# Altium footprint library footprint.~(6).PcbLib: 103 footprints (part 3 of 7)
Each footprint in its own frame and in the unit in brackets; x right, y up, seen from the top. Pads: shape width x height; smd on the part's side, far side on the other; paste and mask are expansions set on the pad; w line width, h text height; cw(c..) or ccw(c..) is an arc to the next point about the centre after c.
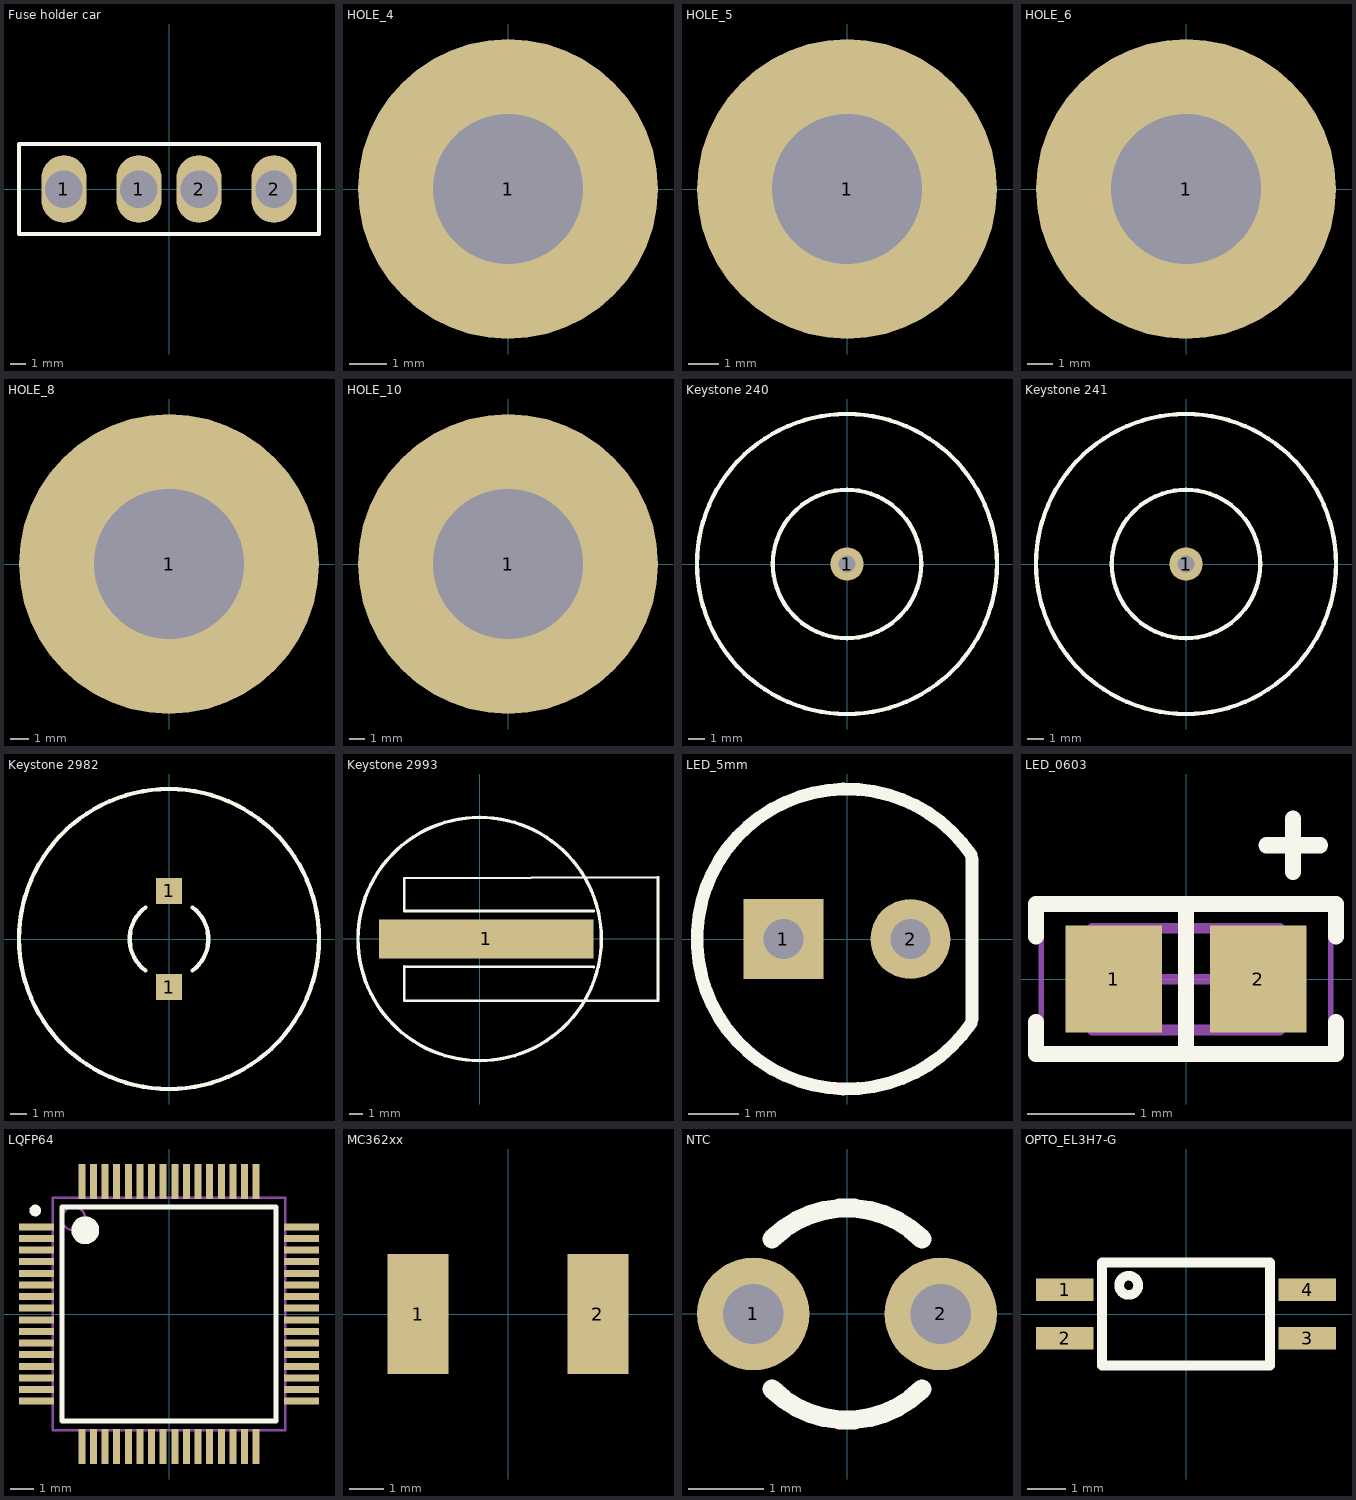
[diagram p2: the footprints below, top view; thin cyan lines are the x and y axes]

## Fuse holder car [mm] "Car fuse holder"
height 8
pads (4):
  oval 3x4.5 hole 2.5: 1(-7,0) 1(-2,0) 2(2,0) 2(7,0)
Top Overlay:
  lines w0.254: -10,-3 10,-3 10,3 -10,3 -10,-3
3D body: height 20, standoff 0, extent -9.5,-2.5 9.5,2.5

## HOLE_4 [mm] "Hole for M4 screw"
pads (1):
  round 8 hole 4: 1(0,0)

## HOLE_5 [mm] "Hole for M5 screw"
pads (1):
  round 10 hole 5: 1(0,0)

## HOLE_6 [mm] "Hole for M6 screw"
pads (1):
  round 12 hole 6: 1(0,0)

## HOLE_8 [mm] "Hole for M8 screw"
pads (1):
  round 16 hole 8: 1(0,0)

## HOLE_10 [mm] "Hole for M10 screw"
pads (1):
  round 20 hole 10: 1(0,0)

## Keystone 240 [mm] "Battery contact Keystone 240"
height 7.6
pads (1):
  round 2 hole 1: 1(0,0)
Top Overlay:
  circle w0.254: c0,0 r9
  circle w0.254: c0,0 r4.45
3D body: height 7.6, standoff 0, extent -4.45,-4.447 4.45,4.447

## Keystone 241 [mm] "Battery contact Keystone 241"
height 1.41
pads (1):
  round 2 hole 1: 1(0,0)
Top Overlay:
  circle w0.254: c0,0 r9
  circle w0.254: c0,0 r4.45
3D body: height 1.41, standoff 0, extent -4.45,-4.447 4.45,4.447

## Keystone 2982 [mil] "Battery contact Keystone 2982"
height 16
pads (2):
  rect 62x62 smd: 1(0,-113.5) 1(0,113.5)
Top Overlay:
  circle w10: c0,0 r354.33
  lines w10: -55.8,-74.4 cw(c0,0) -55.8,74.4 ; 55.8,-74.4 ccw(c0,0) 55.8,74.4
3D body: height 8, standoff 0, extent -31,80 31,144.5
3D body: height 16, standoff 8, extent -92.99,-92.99 93,93
3D body: height 8, standoff 0, extent -31,-144.5 31,-80

## Keystone 2993 [mm] "Battery contact Keystone 2993"
height 2.667
pads (1):
  rect 15.88x2.85 smd: 1(0.49,0)
Top Overlay:
  circle w0.254: c0,0 r9
  lines w0.1: 8.43,-2.07 -5.57,-2.03 -5.57,-4.5 -5.57,-4.57 13.19,-4.57 13.19,4.5 13.19,4.57 -5.57,4.5 -5.57,2.07 8.43,2.07
  lines w0.2: 8.43,-2.07 -5.57,-2.03 -5.57,-4.57 13.19,-4.57 13.19,4.57 -5.57,4.5 -5.57,2.07 8.43,2.07
3D body: height 2.68, standoff 0, extent -5.57,-4.57 13.19,4.5

## LED_5mm [mm]
height 12.7
pads (2):
  rect 1.6x1.6 hole 0.8: 1(-1.27,0)
  round 1.6 hole 0.8: 2(1.27,0)
Top Overlay:
  lines w0.254: 2.481,-1.687 cw(c0,0) 2.481,1.687 ; 2.5,-1.6 2.5,1.6
3D body: height 10.2, standoff 4.9, extent -2.48,-2.495 2.5,2.495
3D body: height 12.7, standoff 7.7, extent -2.474,-2.489 2.5,2.49
3D body: height 4.9, standoff 3.9, extent -3,-3 2.5,3
3D body: height 3.9, standoff -2.6, extent -1.518,-0.249 -1.02,0.25
3D body: height 3.9, standoff -2.6, extent 1.022,-0.249 1.52,0.25

## LED_0603 [mm] "Chip LED, 2-Leads, Body 1.60x0.80mm, IPC Medium Density"
height 1
pads (2):
  rect 0.9x1 smd: 1(-0.675,0) 2(0.675,0)
Top Overlay:
  lines w0.15: -1.4,-0.4 -1.4,-0.7 1.4,-0.7 1.4,-0.4 ; -1.4,0.4 -1.4,0.7 1.4,0.7 1.4,0.4 ; 0,-0.7 0,0.7 ; 0.75,1.25 1.25,1.25 ; 1,1 1,1.5
Mechanical 13:
  lines w0.1: -0.875,-0.475 -0.875,0.475 0.875,0.475 0.875,-0.475 -0.875,-0.475
Mechanical 15:
  lines w0.05: -1.35,-0.75 -1.35,0.75 1.35,0.75 1.35,-0.75 -1.35,-0.75
  lines w0.1: -0.475,0 0.475,0 ; 0,-0.475 0,0.475
3D body "0603 cap.STEP": height 0.82, standoff 0, extent -0.8,-0.412 0.8,0.412

## LQFP64 [mm] "LQFP, 64-Leads, Body 10,00x10,00mm, Pitch 0,50mm, IPC Medium Density"
height 1.6
pads (64):
  rect 1.5x0.3 smd: 1(-5.7,3.75) 2(-5.7,3.25) 3(-5.7,2.75) 4(-5.7,2.25) 5(-5.7,1.75) 6(-5.7,1.25) 7(-5.7,0.75) 8(-5.7,0.25) 9(-5.7,-0.25) 10(-5.7,-0.75) 11(-5.7,-1.25) 12(-5.7,-1.75) 13(-5.7,-2.25) 14(-5.7,-2.75) 15(-5.7,-3.25) 16(-5.7,-3.75) 33(5.7,-3.75) 34(5.7,-3.25) 35(5.7,-2.75) 36(5.7,-2.25) 37(5.7,-1.75) 38(5.7,-1.25) 39(5.7,-0.75) 40(5.7,-0.25) 41(5.7,0.25) 42(5.7,0.75) 43(5.7,1.25) 44(5.7,1.75) 45(5.7,2.25) 46(5.7,2.75) 47(5.7,3.25) 48(5.7,3.75)
  rect 0.3x1.5 smd: 17(-3.75,-5.7) 18(-3.25,-5.7) 19(-2.75,-5.7) 20(-2.25,-5.7) 21(-1.75,-5.7) 22(-1.25,-5.7) 23(-0.75,-5.7) 24(-0.25,-5.7) 25(0.25,-5.7) 26(0.75,-5.7) 27(1.25,-5.7) 28(1.75,-5.7) 29(2.25,-5.7) 30(2.75,-5.7) 31(3.25,-5.7) 32(3.75,-5.7) 49(3.75,5.7) 50(3.25,5.7) 51(2.75,5.7) 52(2.25,5.7) 53(1.75,5.7) 54(1.25,5.7) 55(0.75,5.7) 56(0.25,5.7) 57(-0.25,5.7) 58(-0.75,5.7) 59(-1.25,5.7) 60(-1.75,5.7) 61(-2.25,5.7) 62(-2.75,5.7) 63(-3.25,5.7) 64(-3.75,5.7)
Top Overlay:
  circle w0.25: c-5.75,4.45 r0.125
  circle w0.6: c-3.6,3.6 r0.3
  lines w0.2: -4.6,-4.6 -4.6,4.6 4.6,4.6 4.6,-4.6 -4.6,-4.6
Mechanical 13:
  circle w0.1: c-4.1,4.1 r0.5
  lines w0.1: -5,-5 -5,5 5,5 5,-5 -5,-5
3D body: height 1.6, standoff 0.05, extent -5,-5 5,5

## MC362xx [mm] "Fuse PTC"
height 1.55
pads (2):
  rect 1.78x3.5 smd: 1(-2.615,0) 2(2.615,0)
3D body: height 1.55, standoff 0, extent -2.365,-1.705 2.365,1.705

## NTC [mm] "Trought holl NTC"
height 10
pads (2):
  round 1.5 hole 0.8: 1(-1.25,0) 2(1.25,0)
Top Overlay:
  lines w0.254: -1,-1 ccw(c0,0) 1,-1 ; -1,1 cw(c0,0) 1,1
3D body: height 10, standoff 0, extent -1.488,-1.497 1.5,1.497

## OPTO_EL3H7-G [mm] "optocoupleur"
height 2
pads (4):
  rect 1.5x0.6 smd: 1(-3.175,0.635) 2(-3.175,-0.635) 3(3.175,-0.635) 4(3.175,0.635)
Top Overlay:
  circle w0.254: c-1.5,0.75 r0.25
  lines w0.254: -2.2,-1.35 2.2,-1.35 2.2,1.35 -2.2,1.35 -2.2,-1.35
3D body: height 2.6, standoff 0, extent -2.2,-1.35 2.2,1.35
